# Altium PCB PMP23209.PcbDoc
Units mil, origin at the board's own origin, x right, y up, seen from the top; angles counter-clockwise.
Board outline 1250 x 1072.83 mil, 4 copper layers (Top Layer, Signal Layer 1, Signal Layer 2, Bottom Layer), stack 36.024 mil thick; 28 components, 16 nets, 69 pads, 13 vias.
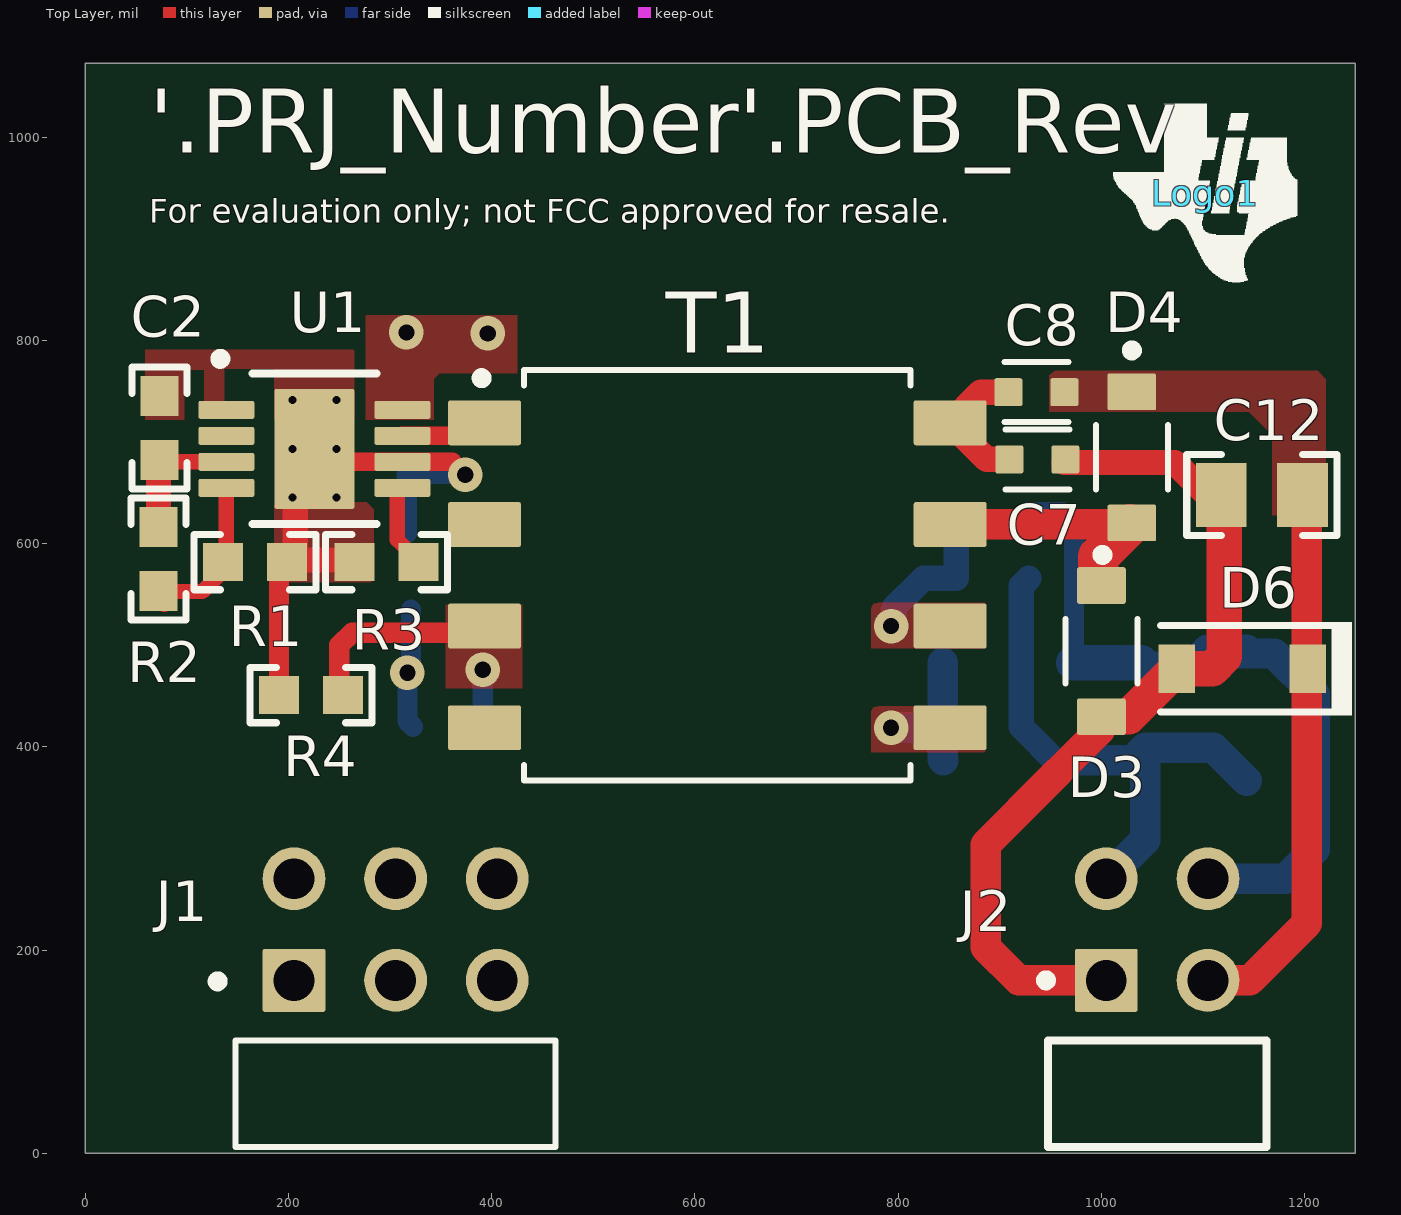
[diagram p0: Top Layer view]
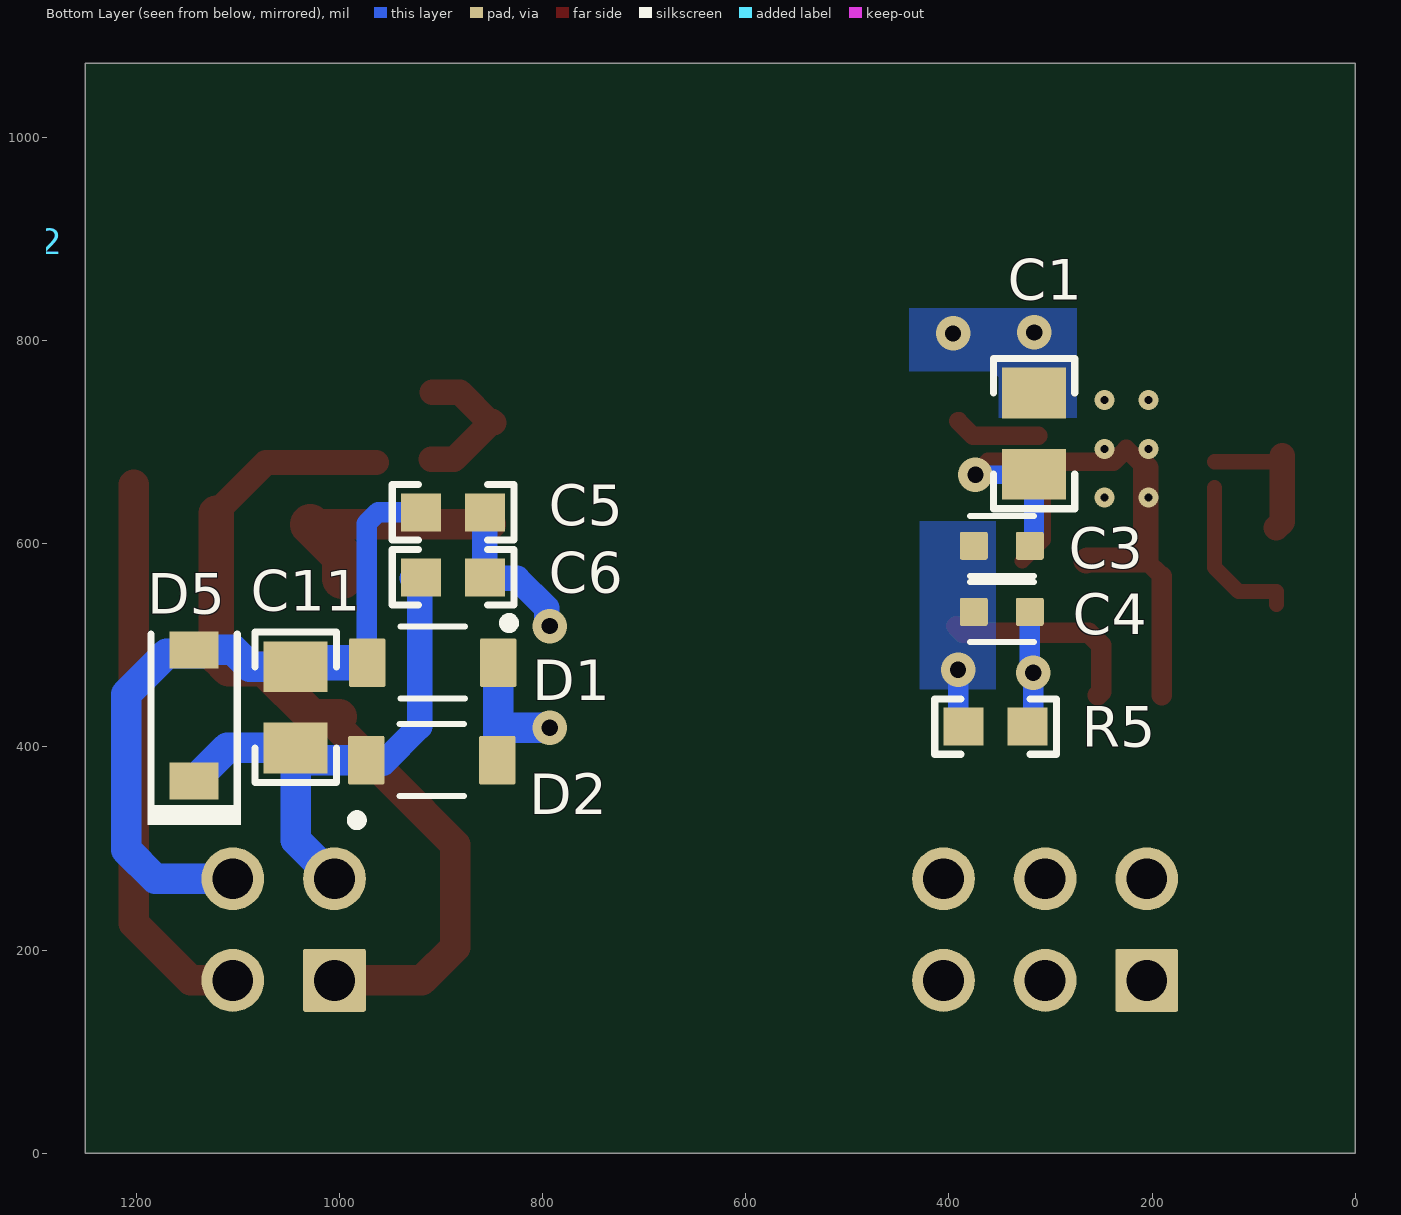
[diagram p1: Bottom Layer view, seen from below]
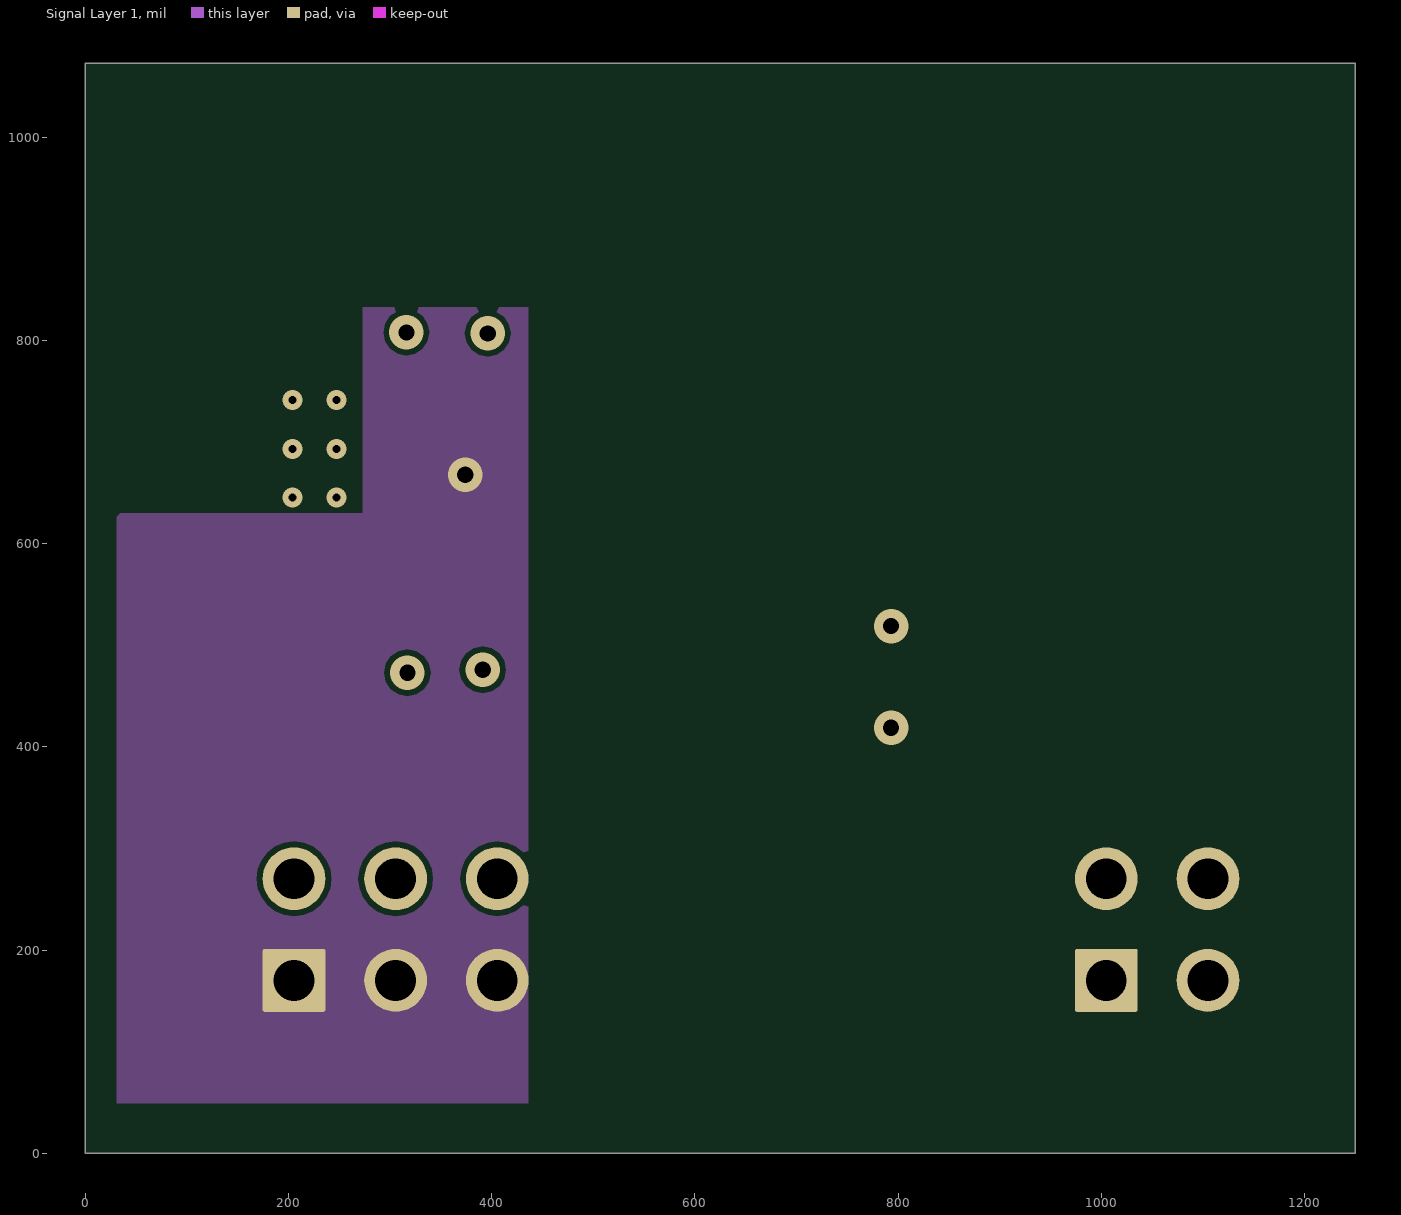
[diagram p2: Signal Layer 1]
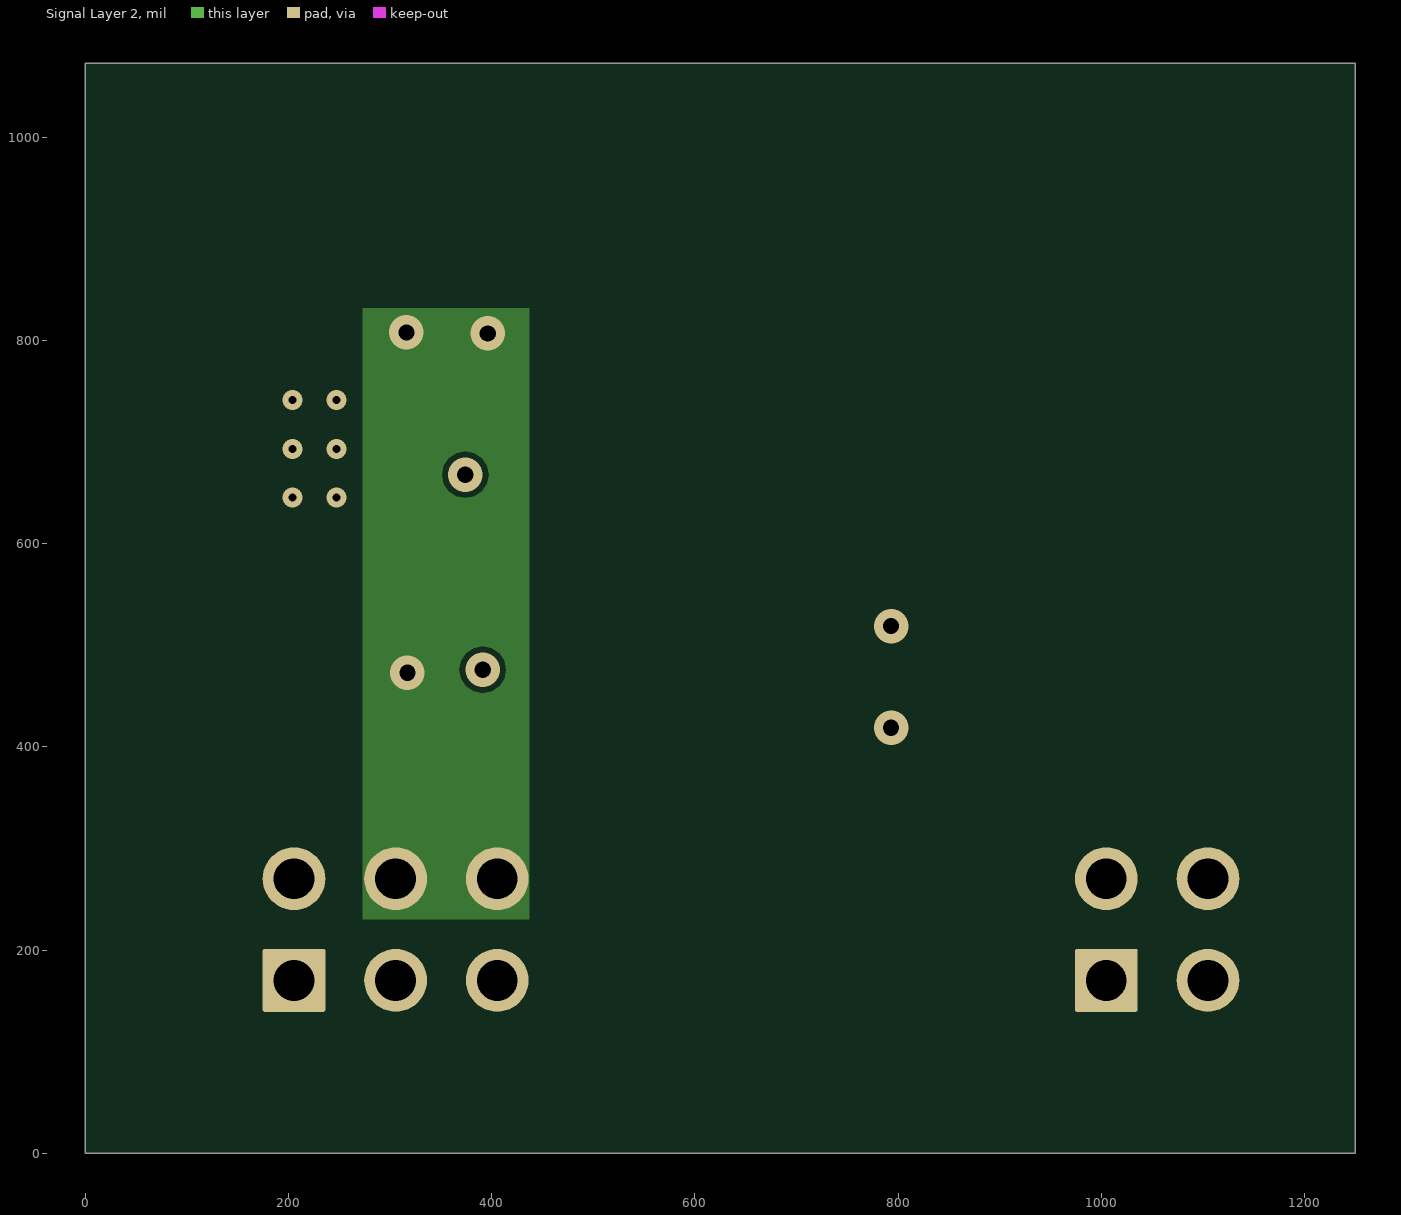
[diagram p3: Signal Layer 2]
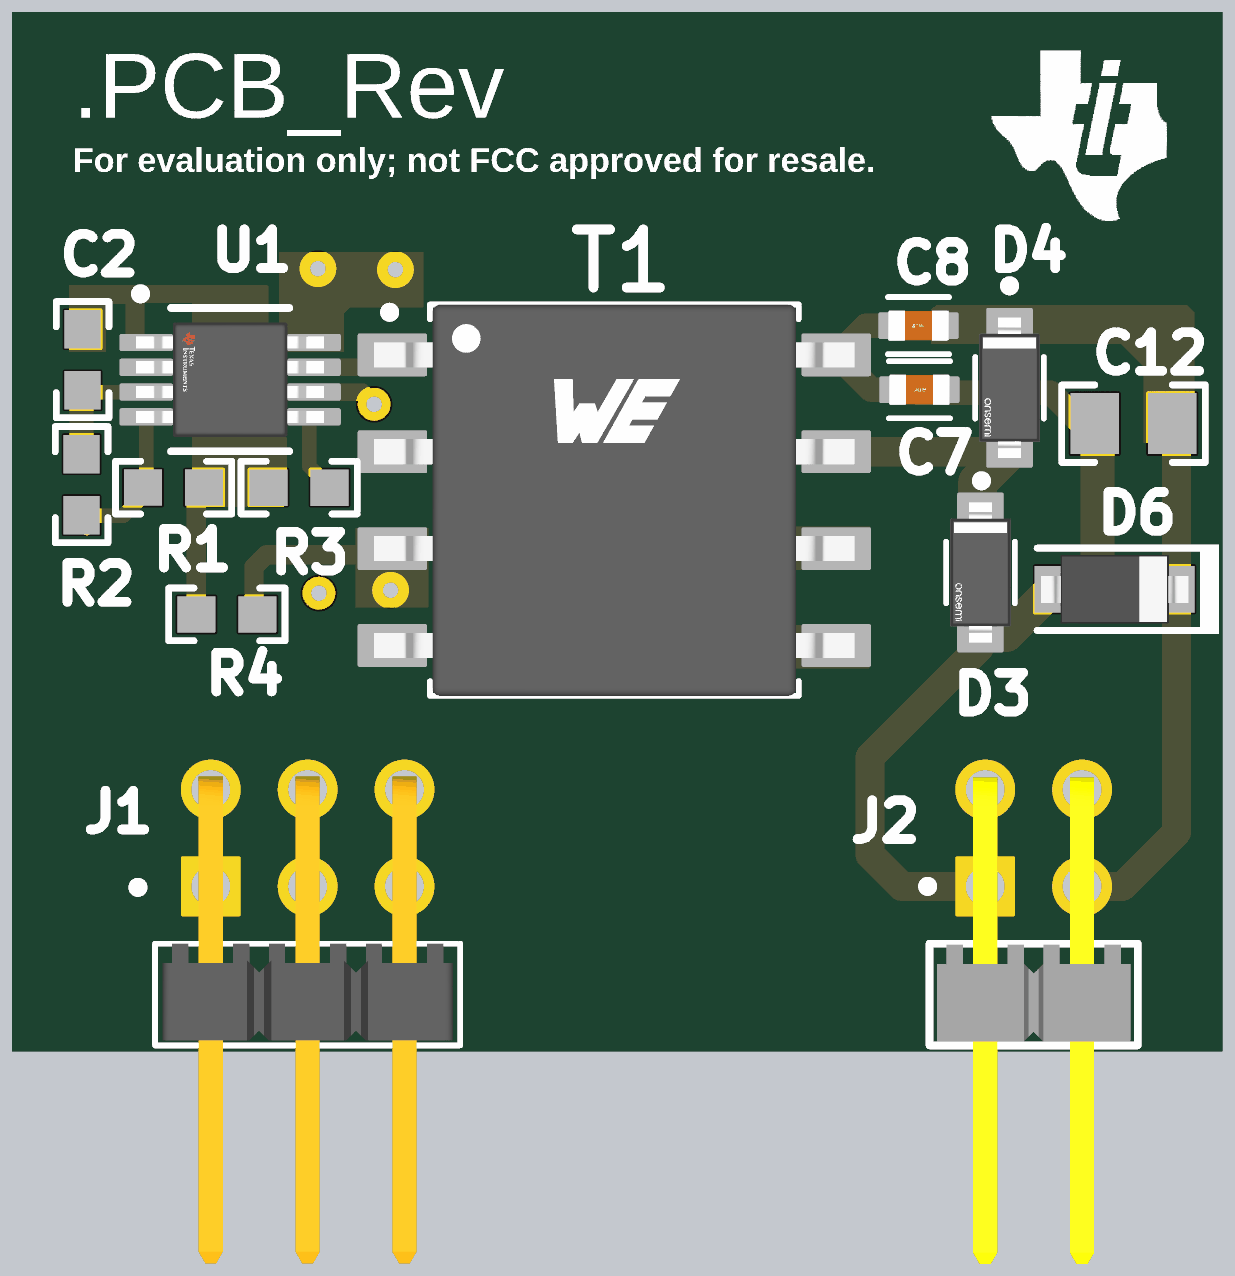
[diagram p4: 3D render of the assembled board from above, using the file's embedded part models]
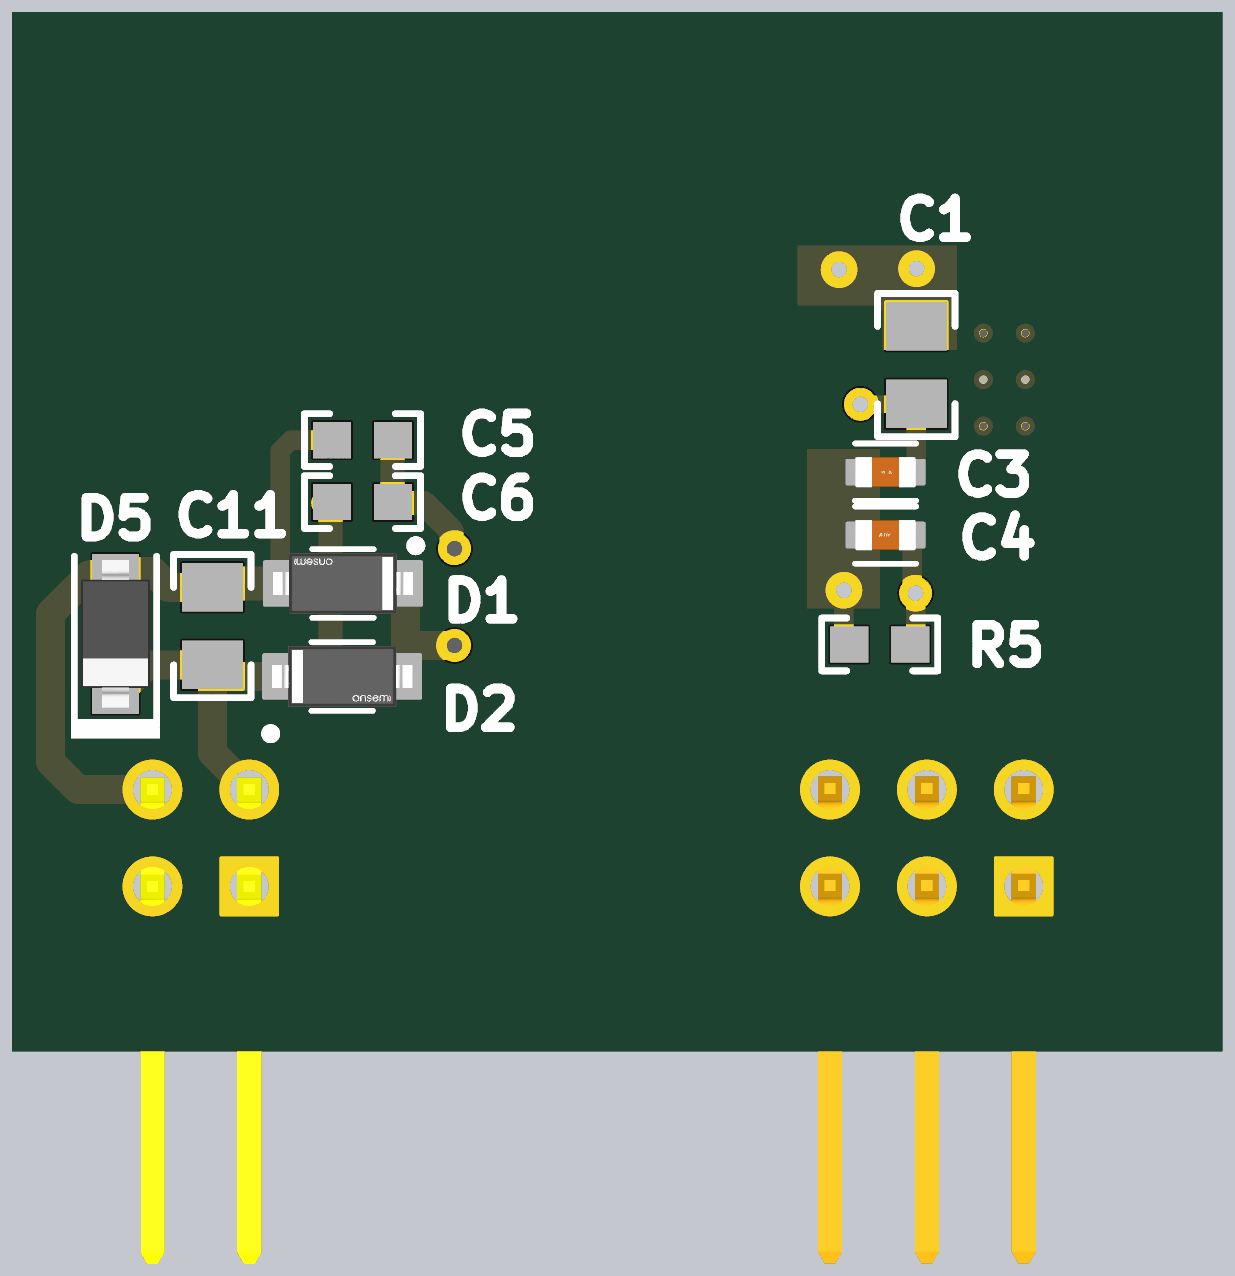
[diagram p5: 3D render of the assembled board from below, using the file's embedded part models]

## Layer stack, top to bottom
Top Solder: solder mask 0.4, Solder Resist, Dk 3.5
Top Layer: signal copper 2.756
Dielectric 2: core 10, FR-4, Dk 4.2
Signal Layer 1: signal copper 2.756
Dielectric1: prepreg 5, FR-4, Dk 4.2
Signal Layer 2: signal copper 2.756
Dielectric 3: core 10, FR-4, Dk 4.2
Bottom Layer: signal copper 2.756
Bottom Solder: solder mask 0.4, Solder Resist, Dk 3.5

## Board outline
0,0 1250,0 1250,1072.83 0,1072.83

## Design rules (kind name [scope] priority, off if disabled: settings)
AcuteAngle [All] p1: minimum=4.50000000000000E+0001 checktracksonly=FALSE
AssemblyTestPointUsage [All] p1: valid=2
BoardOutlineClearance BoardOutlineClearance_MountingHoles [OnCopper and InComponentClass('Mounting Holes')] p1: gap=39.37 ignorepadtopadclearanceinfootprint=FALSE
BoardOutlineClearance BoardOutlineClearance_Poly [OnCopper and IsPoly] p2: gap=25 ignorepadtopadclearanceinfootprint=FALSE
BoardOutlineClearance [OnCopper and Not InComponentClass('Logo') and not InComponentClass('FiducialMark') and not InRegion(1000,500,4000,800) and not InPoly] p3: gap=25 ignorepadtopadclearanceinfootprint=FALSE
Clearance Clearance_SW_PGND [InNetClass('VSWNET') vs InNetClass('PGND')] p1: gap=50 ignorepadtopadclearanceinfootprint=TRUE
Clearance Clearance_Keepouts [((IsTrack Or IsArc) And Not InPoly) And IsFree and IsKeepOut vs ((IsTrack Or IsArc) And Not InPoly) And IsFree and IsKeepOut] p2: gap=0 ignorepadtopadclearanceinfootprint=FALSE
Clearance Clearance_Poly [InPolygon] p3: gap=5.5 ignorepadtopadclearanceinfootprint=TRUE
Clearance Clearance_FiducialMark [IsKeepOut and InComponentClass('FiducialMark') vs IsPad and InComponentClass('FiducialMark')] p4: gap=0 ignorepadtopadclearanceinfootprint=FALSE
Clearance [All] p5: gap=7 ignorepadtopadclearanceinfootprint=TRUE
ComponentClearance ComponentClearance_MountingHoles_FiducialMarks [InComponentClass('Mounting Holes') vs InComponentClass('FiducialMark')] p1: gap=50 collisioncheckmode=3 verticalgap=10 showdistances=FALSE
ComponentClearance ComponentClearance_Shunt [InComponentClass('Header') vs InComponentClass('Shunt')] p2: gap=0 collisioncheckmode=3 verticalgap=0 showdistances=FALSE
ComponentClearance ComponentClearance_Logo [InComponentClass('Logo')] p3: gap=50 collisioncheckmode=3 verticalgap=10 showdistances=FALSE
ComponentClearance ComponentClearance_ScrewToNut [(HasFootprint('NY PMS 440 0025 PH')) vs (HasFootprint('Keystone_1902C'))] p4: gap=5 collisioncheckmode=3 verticalgap=10 showdistances=FALSE
ComponentClearance ComponentClearance_MountingHoles [InComponentClass('Mounting Holes')] p5: gap=250 collisioncheckmode=3 verticalgap=100000 showdistances=FALSE
ComponentClearance ComponentClearance_SmallPassives [HasFootprint('0201*') or HasFootprint('0402*') or HasFootprint('0508') or HasFootprint('0603*') or HasFootprint('0612') or HasFootprint('0805*') or HasFootprint('0815*') or HasFootprint('0830*') or HasFootprint('1206*') or HasFootprint('1210*') or HasFootprint('1808*') or HasFootprint('1812*') or HasFootprint('1825*') or HasFootprint('2010*') or HasFootprint('2220*') or HasFootprint('2225*') or HasFootprint('2512*') or HasFootprint('2728*') or HasFootprint('3518*') vs HasFootprint('0201*') or HasFootprint('0402*') or HasFootprint('0508') or HasFootprint('0603*') or HasFootprint('0612') or HasFootprint('0805*') or HasFootprint('0815*') or HasFootprint('0830*') or HasFootprint('1206*') or HasFootprint('1210*') or HasFootprint('1808*') or HasFootprint('1812*') or HasFootprint('1825*') or HasFootprint('2010*') or HasFootprint('2220*') or HasFootprint('2225*') or HasFootprint('2512*') or HasFootprint('2728*') or HasFootprint('3518*')] p6: gap=14.96 collisioncheckmode=3 verticalgap=10 showdistances=FALSE
ComponentClearance ComponentClearance_THtoSMT [IsThruComponent vs IsSMTComponent] p7: gap=40 collisioncheckmode=3 verticalgap=30 showdistances=FALSE
ComponentClearance ComponentClearance_THtoTH [IsThruComponent vs IsThruComponent] p8: gap=30 collisioncheckmode=3 verticalgap=30 showdistances=FALSE
ComponentClearance [All] p9: gap=30 collisioncheckmode=3 verticalgap=10 showdistances=FALSE
DiffPairsRouting [All] p1: maxlimit=100 minlimit=10 mostfreqgap=10 toplayer_minwidth=15 toplayer_maxwidth=15 toplayer_prefwidth=15 midlayer1_minwidth=15 midlayer1_maxwidth=15 midlayer1_prefwidth=15 midlayer2_minwidth=15 midlayer2_maxwidth=15 midlayer2_prefwidth=15 bottomlayer_minwidth=15 bottomlayer_maxwidth=15 bottomlayer_prefwidth=15 maxuncoupledlength=1000
FabricationTestPointUsage TestPointUsage [All] p1: valid=2 allowmultiple=FALSE
FabricationTestpoint Testpoint [All] p1: side=3 testpointundercomponent=TRUE minsize=40 maxsize=100 preferedsize=60 minholesize=0 maxholesize=40 preferedholesize=32 testpointgrid=1 allowsidetop=TRUE allowsidebottom=TRUE usegrid=TRUE gridtolerance=0.01
FanoutControl Fanout_LCC [IsLCC] p1: bgadir=Out bgaviamode=Centered fanoutstyle=Auto fanoutdirection=Alternating viagrid=1 // Fanout_LCC (Default Rule)
FanoutControl Fanout_BGA [IsBGA] p2: bgadir=Out bgaviamode=Centered fanoutstyle=Auto fanoutdirection=Alternating viagrid=1 // Fanout_BGA (Default Rule)
FanoutControl Fanout_Default [All] p4: bgadir=Out bgaviamode=Centered fanoutstyle=Auto fanoutdirection=Alternating viagrid=1 // Fanout_Default (Default Rule)
FanoutControl Fanout_Small [(CompPinCount < 5)] p5: bgadir=Out bgaviamode=Centered fanoutstyle=Auto fanoutdirection=OutThenIn viagrid=1 // Fanout_Small (Default Rule)
HoleSize [All] p1: absolutevalues=TRUE maxlimit=251 minlimit=7.87 maxpercent=80.000 minpercent=20.000
MinimumAnnularRing MinimumAnnularRing_ThermalPadVias [IsVia and InAnyComponent] p1: minimumring=5.91
MinimumAnnularRing [All] p2: minimumring=7.87
MinimumSolderMaskSliver MinimumSolderMaskSliver_Logo [InComponentClass('Logo') vs InComponentClass('Logo')] p1: minsoldermaskwidth=0.7
MinimumSolderMaskSliver [All] p2: minsoldermaskwidth=3.94
PlaneConnect [All] p1: planeconnectstyle=Direct reliefexpansion=10 reliefentries=4 reliefconductorwidth=10 reliefairgap=10
PolygonConnect [All] p1: connectstyle=Direct reliefconductorwidth=10 reliefentries=4 polygonreliefangle="90 Angle" airgapwidth=10
RoutingVias ThermalPadVias [IsVia and InAnyComponent] p1: holewidth=7.87 width=19.68 viastyle="Through Hole" minholewidth=7.87 minwidth=19.68 maxholewidth=12.99 maxwidth=23.62
RoutingVias [All] p2: holewidth=16 width=34 viastyle="Through Hole" minholewidth=7.87 minwidth=26 maxholewidth=40 maxwidth=65
SilkToBoardRegionClearance [Not ((IsComment or IsDesignator) And (Hide <> 'False')) and not InRegion(1000,500,4000,800)] p1:
SilkToSilkClearance SilkToSilkClearance_Pb-FreeLogo [(HasFootprint('Pb-Free_Overlay_Medium') OR HasFootprint('Pb-Free_Overlay_Small')) vs (HasFootprint('Pb-Free_Overlay_Medium') OR HasFootprint('Pb-Free_Overlay_Small'))] p1: silktosilkclearance=0
SilkToSilkClearance [All] p2: silktosilkclearance=3.94
SilkToSolderMaskClearance SilkToComponentPadClearance [(IsPad or IsFill or IsRegion) and InAnycomponent] p1: minsilkscreentomaskgap=5 clearancetoexposedcopper=TRUE
SilkToSolderMaskClearance "Silk to Solder Mask Opening" [All] p2: minsilkscreentomaskgap=3.94 clearancetoexposedcopper=FALSE
SolderMaskExpansion [All] p1: expansion=1.97
UnRoutedNet [All] p1: checkbadconnections=TRUE
Width [All] p1: maxlimit=100 minlimit=6 preferedwidth=10 checkconnectedcopper=TRUE
14 further rules are at their usual default settings.

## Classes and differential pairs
net class VSWNET: H_XFMR_BOT H_XFMR_TOP HS_GND ISO_12V_H
net class PGND: ISO_12V_L L_XFMR_BOT L_XFMR_TOP LS_GND
net class INGND: 12V_PRI NetU1_2 OC_DT PGND PRI_BOT RT SW VREG
component class PMP23209_sheet1: C1 C2 C3 C4 C5 C6 C7 C8 C11 C12 D1 D2 D3 D4 D5 D6 J1 J2 R1 R2 R3 R4 R5 T1 U1
component class Logo: Logo1
component class PMP23209_Hardware: Logo1 Logo2 Logo3

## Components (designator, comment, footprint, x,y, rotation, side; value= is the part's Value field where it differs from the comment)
C1 "GRM219R61E106KA12D" 0805_HV 316.24,708.5 r270 bottom value=10uF
C2 "GRM185R61A105KE36D" 0603 73,714 r90 top value=1uF
C3 "C1608X8R1E683M080AA" FP-C1608X8R1E683M080AA_0603-MFG 348,598 r0 bottom value=68nF
C4 "C1608X8R1E683M080AA" FP-C1608X8R1E683M080AA_0603-MFG 348,533 r180 bottom value=68nF
C5 "GRM188R61E475KE11D" 0603 888,631 r0 bottom value=4.7uF
C6 "GRM188R61E475KE11D" 0603 888,567 r180 bottom value=4.7uF
C7 "C1608X5R1E475M080AC" FP-C1608X5R1E475M080AC_0603-MFG 937,683 r180 top value=4.7µF
C8 "C1608X5R1E475M080AC" FP-C1608X5R1E475M080AC_0603-MFG 936,749.16 r0 top value=4.7µF
C11 "GRM21BR71E475KA73L" 0805_HV 1043,439 r90 bottom value=4.7uF
C12 "GRM21BR71E475KA73L" 0805_HV 1158,648 r180 top value=4.7uF
D1 "MBR130T3G" FP-MBR130T3G_SOD123-MFG 908.15,483 r0 bottom
D2 "MBR130T3G" FP-MBR130T3G_SOD123-MFG 909,387 r180 bottom
D3 "MBR130T3G" FP-MBR130T3G_SOD123-MFG 1000,494.39 r270 top
D4 "MBR130T3G" FP-MBR130T3G_SOD123-MFG 1030,685 r270 top
D5 "MMSZ4702T1G" SOD-123 1143,431 r90 bottom value=15V
D6 "MMSZ4702T1G" SOD-123 1138.47,477 r180 top value=15V
J1 "TSW-103-08-G-D-RA" FP-TSW-103-08-G-D-RA_HDR6-MFG 305.36,61.22 r0 top locked
J2 "TSW-102-08-G-D-RA" FP-TSW-102-08-G-D-RA_HDR4-MFG 1054.87,61.22 r0 top
Logo1 "Texas Instruments" TI_Symbol_Overlay_Small 1102,945 r0 top
Logo2 "FCC disclaimer" FCC_disclaimer 1325.47,898 r180 bottom
Logo3 "WEEE logo" WEEE_Minimum 2670,490 r0 top
R1 "RT0603DRE0711K4L" 0603 167,582 r180 top value=11.4k
R2 "RT0603BRD073K2L" 0603 72,585 r90 top value=3.20k
R3 "RT0603DRE0750K5L" 0603 296.5,581.93 r0 top value=50.5k
R4 "RT0603BRD073K2L" 0603 222,451 r0 top value=3.20k
R5 "RT0603BRD073K2L" 0603 354,420 r180 bottom value=3.20k
T1 "750319978" FP-750319978_SMT_XFRMR_9MM54_10MM26-MFG 622,569 r0 top locked
U1 "UCC25800DGNRQ1" DGN0008G-MFG 225.38,693.45 r0 top

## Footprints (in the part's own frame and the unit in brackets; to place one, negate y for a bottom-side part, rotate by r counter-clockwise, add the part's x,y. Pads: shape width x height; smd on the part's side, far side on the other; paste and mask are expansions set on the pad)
0603 [mm] "0603 from SM-752 data"
  rect 1x0.95 smd: 1(-0.8,0) 2(0.8,0)
  silkscreen extent -1.52,-0.69 1.52,0.69, body extent -0.87,-0.47 0.87,0.47, height 1
0805_HV [mil] "0805 with 30mil clearance between pads"
  rect 50x63 smd: 1(-40,0) 2(40,0)
  silkscreen extent -74,-40 74,40, body extent -43,-29 43,29, height 57
DGN0008G-MFG [mm]
  rrect22% 1.4x0.45 smd paste+0 mask+0: 1(-2.2,0.975) 2(-2.2,0.325) 3(-2.2,-0.325) 4(-2.2,-0.975) 5(2.2,-0.975) 6(2.2,-0.325) 7(2.2,0.325) 8(2.2,0.975)
  rrect5% 2x3 smd paste-1000 mask-1000: 9(0,0)
  silkscreen extent -2.47,-1.88 1.55,2.37, body extent -2.46,-1.5 2.46,1.5, height 1.1
FCC_disclaimer [mil]
FP-750319978_SMT_XFRMR_9MM54_10MM26-MFG [mm]
  rrect9% 1.82x1.12 smd paste+0 mask+0: 1(-5.82,3.81) 2(-5.82,1.27) 3(-5.82,-1.27) 4(-5.82,-3.81) 5(5.82,-3.81) 6(5.82,-1.27) 7(5.82,1.27) 8(5.82,3.81)
  silkscreen extent -6.02,-5.13 4.83,5.13, body extent -6.83,-5.23 6.83,5.23, height 0.25
FP-C1608X5R1E475M080AC_0603-MFG [mm]
  rrect14% 0.7x0.7 smd paste+0 mask+0: 1(-0.7,0) 2(0.7,0)
  silkscreen extent -0.8,-0.75 0.8,0.75, body extent -1.15,-0.55 1.15,0.55, height 0.25
FP-C1608X8R1E683M080AA_0603-MFG [mm]
  rrect14% 0.7x0.7 smd paste+0 mask+0: 1(-0.7,0) 2(0.7,0)
  silkscreen extent -0.8,-0.75 0.8,0.75, body extent -0.8,-0.4 0.8,0.4, height 0.9
FP-MBR130T3G_SOD123-MFG [mil]
  rrect11% 36x48 smd paste+0 mask+0: 1(-64.5,0) 2(64.5,0)
  silkscreen extent -80,-44 32,35, body extent -72,-31 72,31, height 53
FP-TSW-102-08-G-D-RA_HDR4-MFG [mm]
  rrect6% 1.57x1.57 hole 1.02 paste-1000 mask+0: 1(-1.27,2.77)
  round 1.57 hole 1.02 paste-1000 mask+0: 2(-1.27,5.31) 3(1.27,2.77) 4(1.27,5.31)
  silkscreen extent -2.9,-1.4 2.73,2.89, body extent -2.83,-7.54 2.83,6.2, height 0.25
FP-TSW-103-08-G-D-RA_HDR6-MFG [mm]
  rrect6% 1.57x1.57 hole 1.02 paste-1000 mask+0: 1(-2.54,2.77)
  round 1.57 hole 1.02 paste-1000 mask+0: 2(-2.54,5.31) 3(0,2.77) 4(0,5.31) 5(2.54,2.77) 6(2.54,5.31)
  silkscreen extent -4.57,-1.4 4,2.87, body extent -4.1,-7.54 4.1,6.19, height 0.25
SOD-123 [mm] "On Semi recommended land pattern"
  rect 0.915x1.22 smd: 1(-1.637,0) 2(1.637,0)
  silkscreen extent -2.74,-1.17 2.03,1.17, body extent -1.93,-0.9 1.93,0.9, height 1.35
TI_Symbol_Overlay_Small [mil]
  silkscreen extent -90,-88 91,88
WEEE_Minimum [mil] "WEEElie bin"
  silkscreen extent -95,-172 99,104

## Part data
C1: library part CMP-0008206-2, "CAP, CERM, 10 uF, 25 V, +/- 10%, X5R, 0805", Cap_Case=0805, Manufacturer=MuRata, Supplier Part Number 1=490-7207-1-ND, TempCo=X5R, Tolerance_%=10%, Value1=Unknown, Value2=25V, ValueDisplayed=10uF
C2: library part CMP-0007156-4, "CAP, CERM, 1 uF, 10 V, +/- 10%, X5R, 0603", Cap_Case=0603, Manufacturer=MuRata, Supplier Part Number 1=490-3893-1-ND, TempCo=X5R, Tolerance_%=10%, Value1=Unknown, Value2=10V, ValueDisplayed=1uF
C3 C4: library part CMP-0094554-1, "Multilayer Ceramic Capacitors 68nF ±20% 25V X8R SMD 0603", Manufacturer=TDK, Operating Temperature Range="-55°C to +150°C", TempCo=0.15, Temperature Characteristic=X8R, Tolerance_%=0.2%, ValueDisplayed=68nF, Voltage=50V
C5 C6: library part CMP-0007347-4, "CAP, CERM, 4.7 uF, 25 V, +/- 10%, X5R, 0603", Cap_Case=0603, Manufacturer=MuRata, Supplier Part Number 1=490-7203-1-ND, TempCo=X5R, Tolerance_%=10%, Value1=Unknown, Value2=25V, ValueDisplayed=4.7uF
C7 C8: library part CMP-0094553-1, "Multilayer Ceramic Capacitors 4.7µF ±20% 25V X5R SMD 0603", Manufacturer=TDK, Operating Temperature Range="-55°C to +85°C", TempCo=0.15, Temperature Characteristic=X5R, Tolerance_%=0.2%, ValueDisplayed=4.7µF, Voltage=50V
C11 C12: library part CMP-0008346-2, "CAP, CERM, 4.7 uF, 25 V, +/- 10%, X7R, 0805", Cap_Case=0805, Manufacturer=MuRata, Supplier Part Number 1=490-9962-1-ND, TempCo=X7R, Tolerance_%=10%, Value1=Unknown, Value2=25V, ValueDisplayed=4.7uF
D1 D2 D3 D4: library part CMP-0094495-1, "Diode Schottky 30 V 1A Surface Mount SOD-123", Digikey Part Number=MBR130T3GOSCT-ND, Forward Current=1A, Manufacturer=onsemi, Max Surge Forward Current=5.5A, Mouser Part Number=863-MBR130T3G, Operating Temperature Range="-65°C to +125°C", Peak Reverse Current=60uA
D5 D6: library part CMP-0005745-1, "Diode, Zener, 15 V, 500 mW, SOD-123", Manufacturer="ON Semiconductor", Power_W=500mW, Supplier Part Number 1=MMSZ4702T1GOSCT-ND, Value1=0.5W
J1: library part CMP-0090622-1, "Connector Header Through Hole, Right Angle 6 position 0.100\" (2.54mm)", Current_A=5.7A, Digikey Part Number=SAM1037-03-ND, Manufacturer=Samtec, Mouser Part Number=200-TSW10308GDRA, Operating Temperature Range="-55°C to +125°C", Voltage_V=550V
J2: library part CMP-0088304-1, "CONN HEADER R/A 4POS 2.54MM", Digikey Part Number=SAM1037-02-ND, Manufacturer=Samtec, Mouser Part Number=200-TSW10208GDRA, Operating Temperature Range="-55°C to +125°C"
Logo1: library part CMP-0074838-1, "Texas Instrument Corporate Signature"
Logo2: library part CMP-0074847-1, "FCC_disclaimer"
Logo3: library part CMP-0074769-1
R1: library part CMP-0024611-1, "RES, 11.4 k, 0.5%, 0.1 W, 0603", Manufacturer="Yageo America", Power_W=100mW, TempCo="50 ppm/C", Tolerance_%=0.5%, Value2=0.1W, Value_Code=11k4, ValueDisplayed=11.4k
R2: library part CMP-0024193-2, "RES, 3.20 k, 0.1%, 0.1 W, 0603", Manufacturer="Yageo America", Power_W=100mW, TempCo="25 ppm/C", Tolerance_%=0.1%, Value2=0.1W, Value_Code=3k20, ValueDisplayed=3.20k
R3: library part CMP-0025375-2, "RES, 50.5 k, 0.5%, 0.1 W, 0603", Manufacturer="Yageo America", Power_W=100mW, TempCo="50 ppm/C", Tolerance_%=0.5%, Value2=0.1W, Value_Code=50k5, ValueDisplayed=50.5k
R4 R5: library part CMP-0024193-2, "RES, 3.20 k, 0.1%, 0.1 W, 0603", Manufacturer="Yageo America", Power_W=100mW, TempCo="25 ppm/C", Tolerance_%=0.1%, Value2=0.1W, Value_Code=3k20, ValueDisplayed=100k
T1: library part CMP-0094831-1, "Transformer, 1:1.11:1.11, 0.065Ohm PRI, 0.07Ohm SEC, 141uH, 9.54x10.26x5.38mm, SMT", Manufacturer="Wurth Electronics", Operating Temperature Range="-40°C to +125°C", ValueDisplayed=6.6pF
U1: library part CMP-0088494-2, "Open Loop LLC Transformer Driver for Isolated Bias Supplies", Manufacturer="Texas Instruments", Max Supply Voltage=36V, Min Supply Voltage=12V, Nominal Supply Current=500uA, Operating Temperature Range="-40°C to +150°C", Switching Frequency=100-2000kHz

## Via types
v1: diameter 34, hole 16, Top Layer to Bottom Layer, 7 vias
v2: diameter 19.68, hole 7.87, Top Layer to Bottom Layer, 6 vias

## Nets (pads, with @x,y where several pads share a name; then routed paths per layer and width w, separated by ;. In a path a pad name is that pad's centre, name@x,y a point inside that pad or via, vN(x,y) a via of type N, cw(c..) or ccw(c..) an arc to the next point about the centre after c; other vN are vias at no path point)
5V_PRI: J1.2
12V_PRI: C1.1 C4.2 J1.4 J1.6 R5.2 U1.8 | length 124.4
  Top Layer w20: v1@311.99,803.99 v1(316,808)
  Bottom Layer w20: C4.2@320.44,535 C4.2 320.44,476.44 v1(317,473) 317,425.5 R5.2
  other v1: 396,807
H_XFMR_BOT: D3.1 D4.2 T1.7 | length 246
  Top Layer w30: T1.7 1028.5,619 D4.2
  Top Layer w40: D3.1@997,565.5 997,587.5 D4.2@1028.5,619
H_XFMR_TOP: C7.2 C8.1 T1.8 | length 145.7
  Top Layer w25: T1.8@848.13,719 T1.8@850,720.87 ; C8.1 881.3,749.16 T1.8 887.13,683 C7.2
HS_GND: C7.1 C12.2 D3.2 D6.2 J2.1 | length 858.5
  Top Layer w25: C7.1@963.56,680 1072.27,680 C12.2@1122.35,629.92
  Top Layer w30: D3.2@998.5,416.5 919,337 919,336.69 886,303.69 886,203 918.72,170.28 J2.1
  Top Layer w35: D3.2 1026.89,429.89 D6.2 1109,477 1121,489 C12.2@1121,629.92
ISO_12V_H: C8.2 C12.1 D4.1 D6.1 J2.3 | length 552.4
  Top Layer w30: J2.3 1146.28,170.28 1202.35,226.35 C12.1@1202.35,658
ISO_12V_L: C6.1 C11.1 D2.1 D5.1 J2.2 | length 532.5
  Bottom Layer w25: C6.1@928.5,566 921,558.5 921,420 D2.1@957,384
  Bottom Layer w30: D2.1 1031,387 C11.1 ; J2.2 1043,308.41 C11.1 ; D5.1 1110.53,399 C11.1
L_XFMR_BOT: D1.1 D2.2 T1.5 | length 147
  Bottom Layer w30: v1(793,419) 843.65,419 ; D1.1 843.65,419 ; D2.2 843.65,387.85 843.65,419
L_XFMR_TOP: C5.1 C6.2 T1.6 | length 147.5
  Bottom Layer w25: v1@796,519 796,537 825,566 857,566 C5.1@857,622.5
  other v1: 793,519
LS_GND: C5.2 C11.2 D1.2 D5.2 J2.4 | length 726.5
  Bottom Layer w20: C5.2@928.5,631 962,631 973,620 D1.2@973,483
  Bottom Layer w30: C11.2 1088,479 1104.47,495.47 D5.2 ; J2.4 1181.28,270.28 1210,299 1210,452 1170,492 D5.2@1135,492
  Bottom Layer w35: D1.2 973,483 1039,483 C11.2
OC_DT: R1.2 R2.1 U1.4 | length 162.1
  Top Layer w15: R2.1@77.74,540.19 77.74,552.9 115.14,552.9 138.76,576.52 U1.4
PGND: C1.2 C2.2 C3.1 J1.1 J1.3 J1.5 R1.1 R3.1 R4.1 U1.1 U1.6 U1.9 | length 591.1
  Top Layer w18: R1.1@190.5,568.01 R1.1@206.5,584 ; U1.9@206.5,674.57 U1.9 238.17,680.65 U1.6 361.35,680.65 v1(374,668)
  Top Layer w20: R4.1 R1.1@190.5,568.01
  Top Layer w25: U1.9@206.5,674.57 206.5,584 264,584 R3.1@265,583
  Bottom Layer w18: C1.2 316.74,668 v1(374,668)
  Bottom Layer w20: C3.1@316.24,610.33 C1.2
  other v2: 203.72,645.42 247.03,645.42 203.72,693.45 247.03,693.45 203.72,741.48 247.03,741.48
PRI_BOT: C3.2 C4.1 R4.2 R5.1 T1.3 | length 259.5
  Top Layer w20: R4.2 250,454.5 250,500 262.5,512.5 386.36,512.5 T1.3
  Bottom Layer w20: R5.1 391,425.5 v1(391,476)
RT: R3.2 U1.5 | length 82.8
  Top Layer w15: U1.5 307,650.07 307,603.99 R3.2@327.99,583
SW: T1.1 U1.7 | length 87
  Top Layer w15: T1.1@389.57,722.24 T1.1@390.94,720.87
  Top Layer w18: U1.7 376.32,706.24 T1.1@390.94,720.87
VREG: C2.1 R2.2 U1.3 | length 142.3
  Top Layer w15: C2.1@72,686.59 77.94,680.65 U1.3
  Top Layer w25: C2.1@72,686.59 72,621.63 R2.2@77.74,615.89
pads on no net: T1.2 T1.4 U1.2

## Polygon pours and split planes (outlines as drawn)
L_XFMR_BOT on Top Layer "Top Layer-L_XFMR_BOT" (solid, pour order 46): 773.5,440 773.5,395 884.5,395 885.5,396 885.5,440 776.5,440 775.5,439
L_XFMR_TOP on Top Layer "Top Layer-L_XFMR_TOP 1" (solid, pour order 42): 773.5,542 773.5,497 884.5,497 885.5,498 885.5,542 776.5,542 775.5,541
PGND on Top Layer "Top Layer-PGND" (solid, pour order 40): 187,639 186,638 186,562 286,562 287,563 284,566 284,633.76 276.76,641 255,641
12V_PRI on Top Layer "Top Layer-12V_PRI" (solid, pour order 26): 276,722 276,825 425,825 425,768 349,768 343,762 343,722
PGND on Top Layer "Top Layer-PGND 1" (solid, pour order 0): 59,791.09 263.66,791.09 264.75,790 264.75,722.19 186.01,722.19 186.01,772.33 136.8,772.33 136.8,726 117.11,726 117.11,771.4 97.43,771.4 97.43,722.19 59,722.19
ISO_12V_H on Top Layer "Top Layer-H_VOUT" (solid, pour order 38): 948.81,765.76 948.81,730 1145,730 1168.3,706.7 1168.3,627.96 1221.08,627.96 1221.08,762.16 1212.92,770.32 954.25,770.32
PRI_BOT on Top Layer "Top Layer-PRI_BOT" (solid, pour order 4): 430.2,540.19 354.84,540.19 354.84,458 360,458 430.2,458
L_XFMR_TOP on Bottom Layer "Bottom Layer-L_XFMR_TOP" (solid, pour order 44): 886,652
12V_PRI on Bottom Layer "Bottom Layer-12V_PRI" (solid, pour order 30): 274,724 274,832 439,832 439,770 357,770 351,764 351,724
PRI_BOT on Bottom Layer "Bottom Layer-PRI_BOT" (solid, pour order 36): 354,545.69 354,457 428.91,457 428.91,622 354,622
no net on Bottom Layer "Bottom Layer-No Net" (solid, pour order 6): 334.65,836.61
PGND on Signal Layer 1 "Signal Layer 1-PGND" (solid, pour order 10): 273,630 273,833 436,833 436,49.21 31.09,49.21 30.91,630
12V_PRI on Signal Layer 2 "Signal Layer 2-12V_PRI" (solid, pour order 12): 273,230.4 437,230.4 437,832 273,832

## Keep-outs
Keep-Out Layer:
  text ".Layer_Name" at 577,-858.49 h60

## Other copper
Top Layer:
  text ".Layer_Name" at 577,-858.49 h60
Bottom Layer:
  text ".Layer_Name" at 577,-858.49 h60

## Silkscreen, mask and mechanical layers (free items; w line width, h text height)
Top Overlay:
  text "'.PRJ_Number'.PCB_Rev" at 63,964 h108.27
  text ".Layer_Name" at 577,-858.49 h60
Bottom Overlay:
  text ".Layer_Name" at 577,-858.49 h60
Top Paste:
  text ".Layer_Name" at 577,-858.49 h60
Bottom Paste:
  text ".Layer_Name" at 577,-858.49 h60
Top Solder:
  text ".Layer_Name" at 577,-858.49 h60
  text ".Layer_Name" at 577,-858.49 h60
Bottom Solder:
  text ".Layer_Name" at 577,-858.49 h60
Drill Guide:
  text ".Layer_Name" at 577,-858.49 h60
M1 Board Outline:
  lines w10: 0,0 0,1072.83 ; 0,0 1250,0 ; 0,0 0,1072.84 ; 0,0 1250,0 ; 0,1072.83 1250,1072.83 ; 0,1072.83 1250,1072.83 ; 1250,0 1250,1072.83 ; 1250,0 1250,1072.84
  text ".Layer_Name" at 577,-858.49 h60
M2 Board Dimensions:
  rectangle: 0,-275 125,-150
  rectangle: 125,-400 500,-275
  lines w7: 0,-275 1000,-275 ; 125,-400 125,-150 ; 250,-400 250,-150 ; 500,-400 500,-150 ; 750,-400 750,-150 ; 0,-400 1000,-400 1000,-150 0,-150 0,-400
  text ".Layer_Name" at 577,-858.49 h60
M3 3D STEP Top:
  text ".Layer_Name" at 577,-858.49 h60
M4 3D STEP Bottom:
  text ".Layer_Name" at 577,-858.49 h60
M5 Assembly Top:
  lines w10: -292,-930.17 6308,-930.17 ; -292,-726.83 6310,-726.83 ; -292,-523.5 -292,-1133.5 3713,-1133.5 6310,-1133.5 6310,-523.5 -291.5,-523.5 -291.5,-1133.5 1284,-1133.5 ; 2173,-1133.5 2173,-523.5 ; 3440,-726.83 3440,-523.5 ; 4280,-726.83 4280,-523.5 ; 4902,-1140 4902,-937.17
  text "COMPONENTS MARKED 'DNP' SHOULD NOT BE POPULATED." at 1153.5,-318.5 h60
  text "ASSEMBLY VARIANT:" at 1153,-434 h60
  text ".VariantName" at 2189,-434 h60
  text "PCB VIEWED FROM TOP SIDE" at -228.5,-655.67 h60
  text "BOARD #:" at 2248,-655.67 h60
  text ".PRJ_Number" at 2793.5,-655.67 h60
  text "REV:" at 3638,-655.67 h60
  text ".PCB_Rev" at 3929.5,-655.67 h60
  text "SVN REV:" at 4476,-655.67 h60
  text ".VersionControl_RevNumber" at 4982,-655.67 h60
  text "TID #:" at 2248,-859 h60
  text ".TID" at 2793.5,-859 h60
  text "PLOT NAME =" at -228.5,-1064.34 h60
  text ".plot_File_Name" at 577,-1064.34 h60
  text "GENERATED    :" at 2250,-1064.34 h60
  text ".Print_Date" at 3119.5,-1064.34 h60
  text ".Print_Time" at 3848.5,-1064.34 h60
  text "TEXAS INSTRUMENTS" at 5113,-1064.34 h60
M6 Assembly Bottom:
  lines w10: -292.5,-727.33 6309.5,-727.33 ; -290.5,-930.67 6309.5,-930.67 ; 1115.5,-1140.5 1115.5,-937.67 ; 1737.5,-727.33 1737.5,-524 ; 2577.5,-727.33 2577.5,-524 ; 3844.5,-1134 3844.5,-524 ; 4733.5,-1134 6309,-1134 6309,-524 -292.5,-524 -292.5,-1134 2304.5,-1134 6309.5,-1134 6309.5,-524
  text "COMPONENTS MARKED 'DNP' SHOULD NOT BE POPULATED." at 6102,-318 h60
  text ".VariantName" at 5058,-434 h60
  text "ASSEMBLY VARIANT:" at 6097,-434 h60
  text ".VersionControl_RevNumber" at 1035.5,-656.17 h60
  text "SVN REV:" at 1541.5,-656.17 h60
  text ".PCB_Rev" at 2088,-656.17 h60
  text "REV:" at 2379.5,-656.17 h60
  text ".PRJ_Number" at 3224,-656.17 h60
  text "BOARD #:" at 3769.5,-656.17 h60
  text "PCB VIEWED FROM BOTTOM SIDE" at 6246,-656.17 h60
  text ".TID" at 3224,-859.5 h60
  text "TID #:" at 3769.5,-859.5 h60
  text "TEXAS INSTRUMENTS" at 904.5,-1064.84 h60
  text ".Print_Time" at 2169,-1064.84 h60
  text ".Print_Date" at 2898,-1064.84 h60
  text "GENERATED    :" at 3767.5,-1064.84 h60
  text ".plot_File_Name" at 5440.5,-1064.84 h60
  text "PLOT NAME =" at 6246,-1064.84 h60
M9 Title Sheet:
  drawing of 57 lines, arcs and shapes, not listed
  text "1" at 739.84,8036.5 h70
  text "2" at 3235.5,8036.5 h70
  text "3" at 5724.84,8036.5 h70
  text "4" at 8231.51,8036.5 h70
  text "5" at 10730.5,8036.5 h70
  text "6" at 13235.5,8036.5 h70
  text "A" at -416.5,6893.5 h70
  text "A" at 14383.5,6893.5 h70
  text "B" at -416.5,4513.5 h70
  text "B" at 14383.5,4513.5 h70
  text "C" at -416.5,2138.5 h70
  text "C" at 14383.5,2138.5 h70
  text "PROJECT TITLE:" at 11343.5,277.5 h45
  text ".PRJ_Title" at 11393.5,144.17 h70
  text "DESIGNED FOR:" at 11343.5,-23.5 h45
  text ".PRJ_Customer" at 11393.5,-163.5 h70
  text "D" at -416.5,-231.5 h70
  text "D" at 14383.5,-231.5 h70
  text "FILE NAME:" at 11343.5,-323.5 h45
  text ".PCB_File_Name_No_Path" at 11393.5,-443.5 h70
  text "Texas Instruments (TI) and/or its licensors do not warrant the accuracy or completeness of this specification" at 6374,-605.34 h45
  text "ENGINEER:" at 11343.5,-613.5 h45
  text "LAYOUT BY:" at 12848.5,-613.5 h45
  text "or any information contained therein. TI and/or its licensors do not warrant that this design will meet" at 6329.01,-718 h45
  text ".PRJ_Engineer" at 11393.5,-768.49 h70
  text ".PCB_Layout" at 12899,-768.49 h70
  text "the specifications, will be suitable for your application or fit for any particular purpose, or will operate in" at 6329.01,-830.67 h45
  text ".Layer_Name" at 577,-858.49 h60
  text "ALTIUM DESIGNER VERSION:" at 12848.5,-923.5 h45
  text "an implementation. TI and/or its licensors do not warrant that the design is production worthy. You should" at 6329.01,-943.33 h45
  text "completely validate and test your design implementation to confirm the system functionality for your application." at 6374,-1056 h45
  text ".print_Scale" at 11393.5,-1056.83 h70
  text ".Application_BuildNumber" at 12899,-1056.83 h70
  text "1" at 739.84,-1263.5 h70
  text "2" at 3235.5,-1263.5 h70
  text "3" at 5724.84,-1263.5 h70
  text "4" at 8231.51,-1263.5 h70
  text "5" at 10730.5,-1263.5 h70
  text "6" at 13235.5,-1263.5 h70
M10 Fab Notes:
  drawing of 189 lines, arcs and shapes, not listed
  text "DESIGN INFORMATION" at 12382.02,6356.17 h60
  text "MIN. TRACK WIDTH:" at 11737.46,6224.05 h60
  text "8" at 12833.7,6224.05 h60
  text "MIL" at 12988.46,6224.05 h60
  text "7.874" at 12667.32,6102.36 h60
  text "MIN. CLEARANCE:" at 11737.46,6099.92 h60
  text "MIL" at 12988.46,6099.92 h60
  text "MIN. VIA PAD SIZE:" at 11737.46,5975.8 h60
  text "24" at 12803.71,5975.8 h60
  text "MIL" at 12988.46,5975.8 h60
  text "0.05mm (2MIL)" at 12432.46,5845.9 h60
  text "MINIMUM ANNULAR RING" at 11408.23,5837.67 h60
  text "EXTERNAL" at 13140.46,5837.67 h60
  text "PER" at 11608.23,5727.55 h60
  text "IPC-D-275 CLASS 2 LEVEL C" at 11828.23,5727.54 h60
  text "MIL, HOLES" at 13316.46,5627.07 h60
  text "+/-" at 12924,5618.48 h60
  text "+/-" at 13778,5618.48 h60
  text "REGISTRATION TOLERANCES:" at 11408.23,5617.42 h60
  text "METAL" at 12608,5617.42 h60
  text "5" at 13184.2,5617.42 h60
  text "3" at 14017.2,5617.42 h60
  text "MIL" at 14133.46,5617.42 h60
  text "HOLE SIZE TOLERANCE (UNLESS OTHERWISE SPECIFIED):" at 11408.23,5519.1 h60
  text "+/-" at 13778,5516.23 h60
  text "3" at 14017.2,5515.17 h60
  text "MIL" at 14133.46,5515.17 h60
  text "MATERIAL:" at 11333.46,5377.52 h60
  text "FR-4 High Tg" at 12319.9,5249 h60
  text "X" at 12175.46,5241.01 h60
  text "FR-408" at 11754.46,5236.49 h60
  text "OTHER" at 13242.46,5236.49 h60
  text "62 MIL (1.6mm) +/-10%" at 12074.56,5093.46 h60
  text "X" at 11954.46,5091.01 h60
  text "THICKNESS:" at 11408.23,5085.24 h60
  text "OTHER" at 13359.46,5085.24 h60
  text "TOLERANCE:" at 11408.23,4946.92 h60
  text "X" at 12256.46,4946.92 h60
  text "ANSI IPC-6012 TYPE 3 CLASS 2" at 12434.48,4946.92 h60
  text "OTHER +/-" at 12434.46,4802.73 h60
  text "BOW & TWIST:" at 11408.23,4657.54 h60
  text "X" at 12256.46,4657.54 h60
  text "ANSI IPC-6012 TYPE 3 CLASS 2" at 12434.48,4657.54 h60
  text "OTHER +/-" at 12434.46,4510.85 h60
  text "DRILLING:" at 11333.46,4380.23 h60
  text "NC_DRILL FILES" at 13094.46,4275.04 h60
  text "REFERENCE:" at 11408.23,4271.1 h60
  text "X" at 12065.46,4271.01 h60
  text "AS SHOWN" at 12243.46,4271.1 h60
  text "X" at 12966.46,4271.1 h60
  text "OTHER" at 13392.46,4128.85 h60
  text "PTH COPPER THICKNESS:" at 11407.91,4125.32 h60
  text "X" at 12547.14,4125.32 h60
  text "20-30 um" at 12675.14,4125.32 h60
  text "BOARD FINISH:" at 11333.46,3977.73 h60
  text "SILKSCREEN:" at 11488.68,3867.6 h60
  text "X" at 12446.46,3867.6 h60
  text "TOP" at 12563.46,3867.6 h60
  text "X" at 12956.46,3867.6 h60
  text "BOTTOM" at 13074.46,3867.6 h60
  text "SILKSCREEN COLOR:" at 11488.68,3712.41 h60
  text "X" at 12445.46,3712.41 h60
  text "WHITE" at 12563.46,3712.41 h60
  text "OTHER" at 13074.46,3712.41 h60
  text "X" at 12576.46,3568.96 h60
  text "GREEN" at 12694.46,3568.96 h60
  text "OTHER" at 13312.46,3568.96 h60
  text "SOLDER RESIST COLOR:" at 11488.68,3562.1 h60
  text "X" at 12576.46,3414.71 h60
  text "MATTE" at 12694.46,3414.71 h60
  text "SEMI-GLOSS" at 13312,3414.07 h60
  text "IMMERSION GOLD (ENIG)" at 12394.46,3241.94 h60
  text "ENEPIG" at 13732,3234.72 h60
  text "SURFACE FINISH:" at 11333.46,3233.72 h60
  text "IMM. TIN/SILVER OR EQUIV" at 11663,3096.4 h60
  text "X" at 12918.99,3095.92 h60
  text "OTHER" at 13094.46,3092.47 h60
  text "ARRAY/PANEL:" at 11333.46,2937.09 h60
  text "CUT AND TRIM PER M1 BOARD OUTLINE" at 12394.46,2928.87 h60
  text "N.C. ROUTE" at 12394.46,2792.9 h60
  text "X" at 13082.46,2792.9 h60
  text "V. SCORE" at 13260.46,2792.9 h60
  text "CERTIFICATION:" at 11333.46,2663.77 h60
  text "MATERIALS AND WORKMANSHIP FOR ALL PCBS" at 12058.46,2663.77 h60
  text "TO MEET OR EXCEED THE REQUIREMENTS OF:" at 12058.46,2569.71 h60
  text "X" at 11695.97,2441.08 h60
  text "ANSI IPC-A-600F CLASS ->" at 11823.96,2441.08 h60
  text "X" at 13471.97,2441.08 h60
  text "2" at 13581.96,2441.08 h60
  text "1" at 13266.96,2439.58 h60
  text "3" at 13935.96,2439.58 h60
  text "X" at 12507.97,2293.39 h60
  text "RoHS" at 12635.96,2293.39 h60
  text "OTHER" at 13280.36,2293.39 h60
  text "PER ORDER" at 13677.42,2293.39 h60
  text "ALL BOARDS MUST MEET OR EXCEED UL94-V0 REQUIREMENTS." at 11361,2139.57 h60
  text "PCB MUST BEAR THE UL94V-0 UL REGISTERED MATERIAL ID NUMBER" at 11361,2023.5 h60
  text "ADDITIONAL REQUIREMENTS:" at 11333.46,1854.08 h60
  text "MICROSECTION:" at 11408.23,1746.95 h60
  text "YES" at 12313.96,1746.95 h60
  text "REQUIRED" at 13175.46,1602.62 h60
  text "BARE BOARD ELEC. TEST:" at 11408.23,1599.76 h60
  text "X" at 12591.1,1599.76 h60
  text "NONE" at 12713.96,1599.76 h60
  text "PER ORDER" at 13767.46,1599.76 h60
  text "XX MIL VIAS REQUIRE NON-CONDUCTIVE FILL AND PLANARIZE" at 11576.38,1394.82 h59
  text "XX MIL VIAS REQUIRE CONDUCTIVE FILL AND PLANARIZE" at 11584.38,1290.84 h60
  text "OUTER XX MIL TRACES REQUIRE 50 OHM SINGLE-ENDED IMPEDANCE" at 11583.39,1127.46 h58
  text "LAYER 2 & 3 (INNER LAYERS) XX MIL WIDE, XX MIL SPACE / TRACES REQUIRE 100 OHM DIFFERENTIAL IMPEDANCE" at 11575.39,891.74 h60
  text ".Layer_Name" at 577,-858.49 h60
M11 Gerber Information:
  lines w10: -292,-930.17 6308,-930.17 ; -292,-726.83 6310,-726.83 ; -292,-523.5 -292,-1133.5 3713,-1133.5 6310,-1133.5 6310,-523.5 -291.5,-523.5 -291.5,-1133.5 1284,-1133.5 ; 2173,-1133.5 2173,-523.5 ; 3440,-726.83 3440,-523.5 ; 4280,-726.83 4280,-523.5 ; 4902,-1140 4902,-937.17
  text "ALL ARTWORK VIEWED FROM TOP SIDE" at -228.5,-655.67 h60
  text "BOARD #:" at 2248,-655.67 h60
  text ".PRJ_Number" at 2793.5,-655.67 h60
  text "REV:" at 3638,-655.67 h60
  text ".PCB_Rev" at 3929.5,-655.67 h60
  text "SVN REV:" at 4476,-655.67 h60
  text ".VersionControl_RevNumber" at 4982,-655.67 h60
  text "LAYER NAME =" at -228.5,-858.49 h60
  text "TID #:" at 2248,-859 h60
  text ".TID" at 2793.5,-859 h60
  text "PLOT NAME =" at -228.5,-1064.34 h60
  text ".plot_File_Name" at 577,-1064.34 h60
  text "GENERATED    :" at 2250,-1064.34 h60
  text ".Print_Date" at 3119.5,-1064.34 h60
  text ".Print_Time" at 3848.5,-1064.34 h60
  text "TEXAS INSTRUMENTS" at 5113,-1064.34 h60
M12 Stackup:
  drawing of 295 lines, arcs and shapes, not listed
  text "Layer" at 6579.95,6330.24 h60
  text "Name" at 6989.86,6330.24 h60
  text "Material" at 7929.6,6330.24 h60
  text "Thickness" at 8789.37,6330.24 h60
  text "Constant" at 9439.21,6330.24 h60
  text "Board Layer Stack" at 10009.07,6330.24 h60
  text "1" at 6579.95,6210.24 h60
  text "Top Overlay" at 6989.86,6210.24 h60
  text "2" at 6579.95,6090.24 h60
  text "Top Solder" at 6989.86,6090.24 h60
  text "Solder Resist" at 7929.6,6090.24 h60
  text "0.40mil" at 8789.37,6090.24 h60
  text "3.5" at 9439.21,6090.24 h60
  text "3" at 6579.95,5970.24 h60
  text "Top Layer" at 6989.86,5970.24 h60
  text "Copper" at 7929.6,5970.24 h60
  text "2.76mil" at 8789.37,5970.24 h60
  text "4" at 6579.95,5850.24 h60
  text "Dielectric 2" at 6989.86,5850.24 h60
  text "FR-4" at 7929.6,5850.24 h60
  text "10.00mil" at 8789.37,5850.24 h60
  text "4.2" at 9439.21,5850.24 h60
  text "5" at 6579.95,5730.24 h60
  text "Signal Layer 1" at 6989.86,5730.24 h60
  text "Copper" at 7929.6,5730.24 h60
  text "2.76mil" at 8789.37,5730.24 h60
  text "6" at 6579.95,5610.24 h60
  text "Dielectric1" at 6989.86,5610.24 h60
  text "FR-4" at 7929.6,5610.24 h60
  text "5.00mil" at 8789.37,5610.24 h60
  text "4.2" at 9439.21,5610.24 h60
  text "7" at 6579.95,5490.24 h60
  text "Signal Layer 2" at 6989.86,5490.24 h60
  text "Copper" at 7929.6,5490.24 h60
  text "2.76mil" at 8789.37,5490.24 h60
  text "8" at 6579.95,5370.24 h60
  text "Dielectric 3" at 6989.86,5370.24 h60
  text "FR-4" at 7929.6,5370.24 h60
  text "10.00mil" at 8789.37,5370.24 h60
  text "4.2" at 9439.21,5370.24 h60
  text "9" at 6579.95,5250.24 h60
  text "Bottom Layer" at 6989.86,5250.24 h60
  text "Copper" at 7929.6,5250.24 h60
  text "2.76mil" at 8789.37,5250.24 h60
  text "10" at 6579.95,5130.24 h60
  text "Bottom Solder" at 6989.86,5130.24 h60
  text "Solder Resist" at 7929.6,5130.24 h60
  text "0.40mil" at 8789.37,5130.24 h60
  text "3.5" at 9439.21,5130.24 h60
  text "11" at 6579.95,5010.24 h60
  text "Bottom Overlay" at 6989.86,5010.24 h60
  text ".Layer_Name" at 577,-858.49 h60
M13 Component Bodies Top:
  text ".Layer_Name" at 577,-858.49 h60
M14 Component Bodies Bottom:
  text ".Layer_Name" at 577,-858.49 h60
M15 Courtyards Top:
  text ".Layer_Name" at 577,-858.49 h60
M16 Courtyards Bottom:
  text ".Layer_Name" at 577,-858.49 h60
Drill Drawing:
  circle w10: c476.76,2464.44 r33.33
  lines w10: 443.43,2281.1 510.09,2281.1 510.09,2347.77 443.43,2347.77 443.43,2281.1 ; 443.43,2647.77 510.09,2647.77 476.76,2581.1 443.43,2647.77
  lines w15: 383.64,2236.1 10854.74,2236.1 ; 383.64,2686.1 10854.74,2686.1 ; 934.51,2086.1 934.51,2836.1 ; 1474.37,2086.1 1474.37,2836.1 ; 2564.06,2086.1 2564.06,2836.1 ; 3069.93,2086.1 3069.93,2836.1 ; 3803.73,2086.1 3803.73,2836.1 ; 5303.28,2086.1 5303.28,2836.1 ; 5893.13,2086.1 5893.13,2836.1 ; 6638.93,2086.1 6638.93,2836.1 ; 7288.76,2086.1 7288.76,2836.1 ; 8142.52,2086.1 8142.52,2836.1 ; 9476.13,2086.1 9476.13,2836.1 ; 383.64,2086.1 10854.74,2086.1 10854.74,2836.1 383.64,2836.1 383.64,2086.1
  text "Symbol" at 473.64,2731.1 h72
  text "Count" at 979.51,2731.1 h72
  text "Hole Size" at 1519.37,2731.1 h72
  text "Plated" at 2609.06,2731.1 h72
  text "Hole Type" at 3114.93,2731.1 h72
  text "Drill Layer Pair" at 3848.73,2731.1 h72
  text "Via/Pad" at 5348.28,2731.1 h72
  text "Pad Shape" at 5938.13,2731.1 h72
  text "Template" at 6683.93,2731.1 h72
  text "Description" at 7333.76,2731.1 h72
  text "Hole Tolerance (+)" at 8187.52,2731.1 h72
  text "Hole Tolerance (-)" at 9521.13,2731.1 h72
  text "6" at 979.51,2581.1 h60
  text "0.200mm (7.87mil)" at 1519.37,2581.1 h60
  text "PTH" at 2609.06,2581.1 h60
  text "Round" at 3114.93,2581.1 h60
  text "Top Layer - Bottom Layer" at 3848.73,2581.1 h60
  text "Via" at 5348.28,2581.1 h60
  text "Rounded" at 5938.13,2581.1 h60
  text "v50h20m50" at 6683.93,2581.1 h60
  text "7" at 979.51,2431.1 h60
  text "0.406mm (16.00mil)" at 1519.37,2431.1 h60
  text "PTH" at 2609.06,2431.1 h60
  text "Round" at 3114.93,2431.1 h60
  text "Top Layer - Bottom Layer" at 3848.73,2431.1 h60
  text "Via" at 5348.28,2431.1 h60
  text "Rounded" at 5938.13,2431.1 h60
  text "v86h41" at 6683.93,2431.1 h60
  text "10" at 979.51,2281.1 h60
  text "1.020mm (40.16mil)" at 1519.37,2281.1 h60
  text "PTH" at 2609.06,2281.1 h60
  text "Round" at 3114.93,2281.1 h60
  text "Top Layer - Bottom Layer" at 3848.73,2281.1 h60
  text "Pad" at 5348.28,2281.1 h60
  text "(Mixed)" at 5938.13,2281.1 h60
  text "(Mixed)" at 6683.93,2281.1 h60
  text "23 Total" at 979.51,2131.1 h60
  text ".Layer_Name" at 577,-858.49 h60
M17 Embedded Cavity:
  text ".Layer_Name" at 577,-858.49 h60
M18 Embedded Assembly:
  text ".Layer_Name" at 577,-858.49 h60
M19 Embedded Keepout:
  text ".Layer_Name" at 577,-858.49 h60

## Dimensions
0,-400 to 1000,-400 on M2 Board Dimensions
0,0 to 0,1072.83 on M2 Board Dimensions
0,0 to 1250,0 on M2 Board Dimensions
